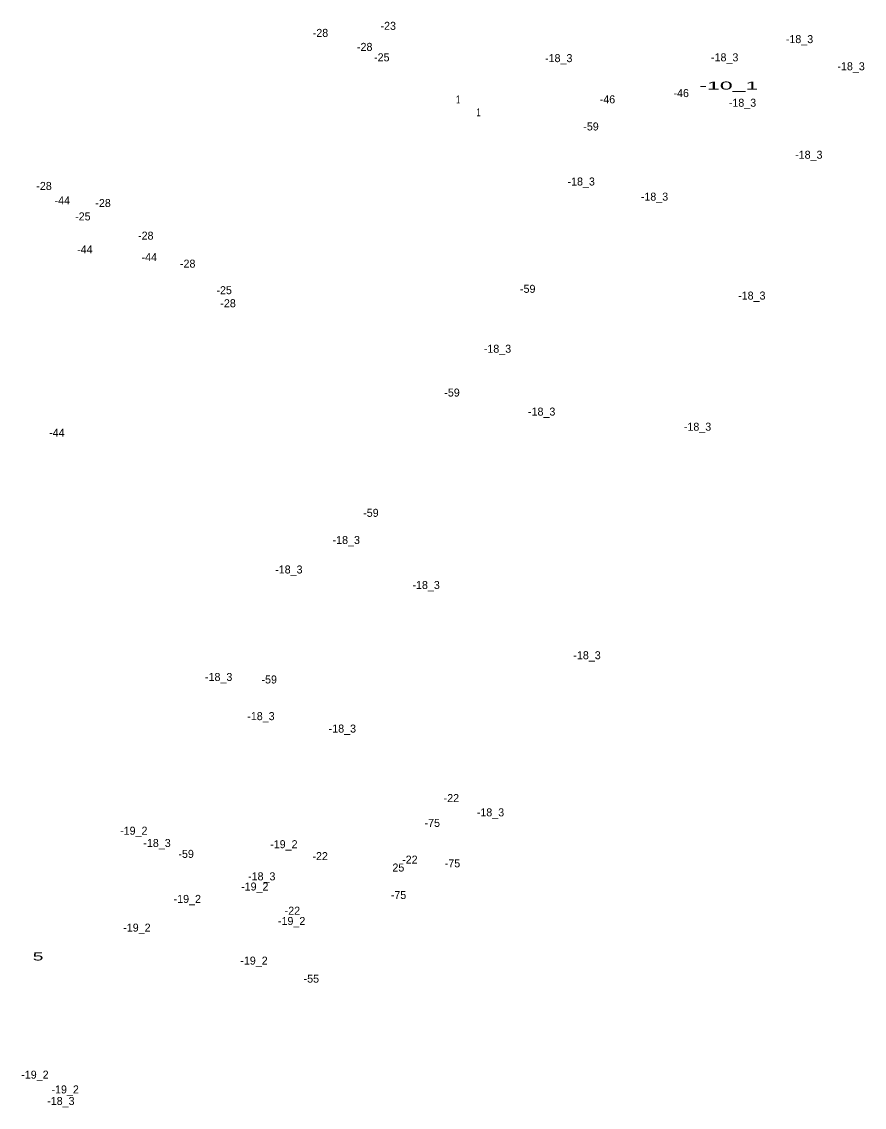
# Model space of a CAD drawing. Extents: x -657046 to -655830, y -1000534 to -999433.
# Drawn here: x -656334 to -655913, y -1000521 to -999979 of the extents above; entities that cross this region are included whole.
import ezdxf
from ezdxf.enums import TextEntityAlignment as Align

# ---------------------------------------------------------------- set-up
doc = ezdxf.new("R2010")
doc.units = 0
doc.header["$LTSCALE"] = 1.6
doc.layers.add('24', color=7, linetype='Continuous')

msp = doc.modelspace()

# ---------------------------------------------------------------- texts
at = {"layer": '24'}
for s, p in [('-23', (-656150.615, -999982.78)), ('-28', (-656184.495, -999986.31)), ('-18_3', (-655944.986, -999989.42)), ('-28', (-656162.375, -999993.3)), ('-25', (-656153.835, -999998.52)), ('-18_3', (-656065.376, -999998.93)), ('-18_3', (-655982.396, -999998.54)), ('-18_3', (-655919.196, -1000003)), ('-46', (-656004.135, -1000016.41)), ('-46', (-656041.015, -1000019.52)), ('-18_3', (-655973.486, -1000021.23)), ('-59', (-656049.23, -1000033.08)), ('-18_3', (-655940.336, -1000047.22)), ('-18_3', (-656054.136, -1000060.6)), ('-28', (-656322.705, -1000062.82)), ('-44', (-656313.563, -1000070.06)), ('-28', (-656293.195, -1000071.36)), ('-18_3', (-656017.486, -1000068.16)), ('-25', (-656303.295, -1000078.04)), ('-28', (-656271.845, -1000087.67)), ('-44', (-656302.303, -1000094.53)), ('-44', (-656270.083, -1000098.41)), ('-28', (-656250.885, -1000101.65)), ('-25', (-656232.645, -1000114.93)), ('-59', (-656080.87, -1000114.24)), ('-28', (-656230.695, -1000121.45)), ('-18_3', (-655968.826, -1000117.62)), ('-18_3', (-656095.996, -1000144.2)), ('-59', (-656118.72, -1000166.09)), ('-18_3', (-656073.896, -1000175.62)), ('-44', (-656316.273, -1000186.15)), ('-18_3', (-655995.966, -1000183.18)), ('-59', (-656159.27, -1000226.23)), ('-18_3', (-656171.606, -1000239.81)), ('-18_3', (-656200.306, -1000254.55)), ('-18_3', (-656131.666, -1000262.31)), ('-18_3', (-656051.216, -1000297.41)), ('-18_3', (-656235.396, -1000308.27)), ('-59', (-656210.12, -1000309.53)), ('-18_3', (-656214.266, -1000327.86)), ('-18_3', (-656173.546, -1000334.07)), ('-22', (-656119.045, -1000368.82)), ('-18_3', (-656099.496, -1000375.96)), ('-75', (-656128.591, -1000381.24)), ('-19_2', (-656277.832, -1000385.14)), ('-18_3', (-656266.216, -1000391.27)), ('-19_2', (-656202.802, -1000391.88)), ('-59', (-656251.66, -1000396.72)), ('-22', (-656184.655, -1000397.85)), ('25', (-656145.547, -1000403.55)), ('-22', (-656139.815, -1000399.6)), ('-75', (-656118.501, -1000401.44)), ('-18_3', (-656213.866, -1000407.95)), ('-19_2', (-656217.342, -1000413.03)), ('-19_2', (-656251.082, -1000419.23)), ('-75', (-656145.481, -1000417.27)), ('-22', (-656198.535, -1000425.13)), ('-19_2', (-656198.922, -1000430.28)), ('-19_2', (-656276.282, -1000433.58)), ('-19_2', (-656217.732, -1000450.07)), ('-55', (-656189.065, -1000459.09)), ('-19_2', (-656327.272, -1000507.09)), ('-19_2', (-656312.142, -1000514.46)), ('-18_3', (-656314.296, -1000520.24))]:
    msp.add_text(s, height=4, dxfattribs=at).set_placement(p, align=Align.CENTER)
for s, width, p in [('-10_1', 2.15, (-655980.334, -1000012.64)), ('1', 0.65, (-656115.687, -1000019.59)), ('1', 0.65, (-656105.397, -1000026)), ('5', 1.8, (-656325.691, -1000448.01))]:
    msp.add_text(s, height=4, dxfattribs=dict(at, width=width)).set_placement(p, align=Align.CENTER)

doc.saveas('drawing.dxf')
